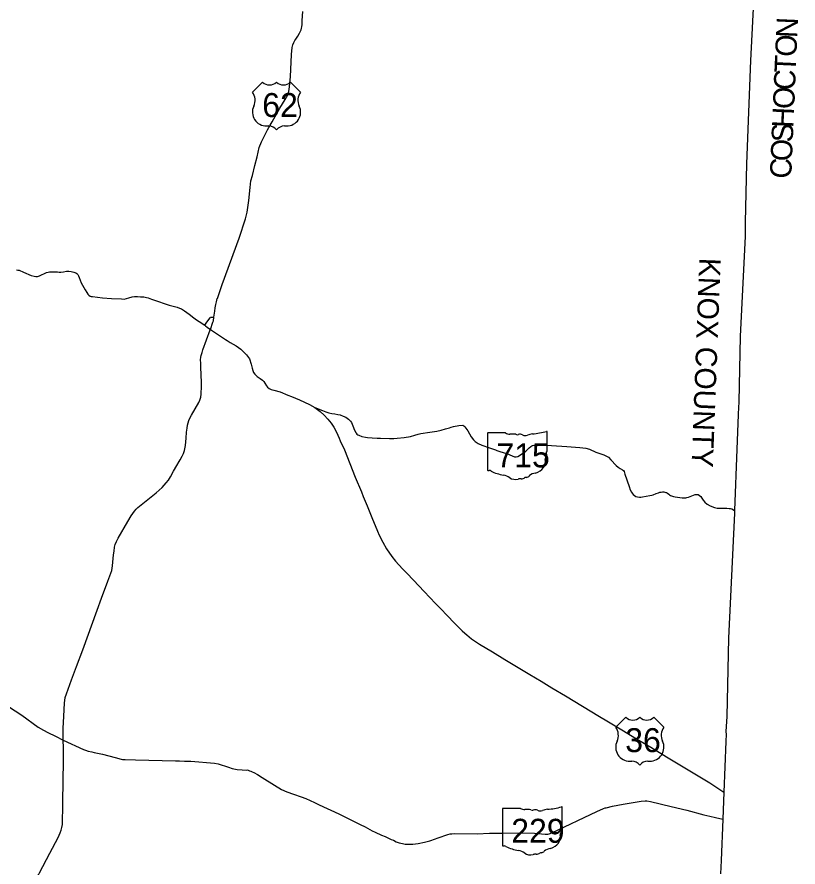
# Model space of a CAD drawing. Extents: x 1851937 to 2123937, y 789467 to 965467.
# Drawn here: x 2021685 to 2058232, y 848684 to 888471 of the extents above; entities that cross this region are included whole.
import ezdxf

# ---------------------------------------------------------------- set-up
doc = ezdxf.new("R2010")
doc.units = 0
for name, color, linetype in [('GM_X_County', 7, 'Continuous'), ('GM_X_County_Text', 7, 'Continuous'), ('GM_X_State_Location', 7, 'Continuous'), ('GM_X_State_Route', 7, 'Continuous'), ('GM_X_State_Shield', 7, 'Continuous'), ('GM_X_US_Location', 7, 'Continuous'), ('GM_X_US_Route', 7, 'Continuous'), ('GM_X_US_Shield', 7, 'Continuous')]:
    doc.layers.add(name, color=color, linetype=linetype)

msp = doc.modelspace()

# ---------------------------------------------------------------- linework, layer by layer
at = {"layer": 'GM_X_County'}
msp.add_lwpolyline([(2056177, 889807), (2056002, 886440), (2055829, 881600), (2055757, 878860), (2055763, 878218), (2055528, 873511), (2055458, 870451), (2055436, 869891), (2055434, 869842), (2055375, 868236), (2055262, 865369), (2055260, 865250), (2054985, 859397), (2054895, 855723), (2054855, 855032), (2054877, 854884), (2054856, 854579), (2054855, 854554), (2054764, 852183), (2054712, 850926), (2054638, 848994), (2054606, 848369)], dxfattribs=at)
at = {"layer": 'GM_X_State_Route'}
msp.add_line((2052003, 866233), (2052042, 866219), dxfattribs=at)
for points in [[(2035622, 870200), (2035980, 870055), (2036138, 869993), (2036279, 869945), (2036417, 869913), (2036558, 869892), (2036695, 869872), (2036812, 869847), (2036953, 869792), (2037068, 869733), (2037193, 869644), (2037289, 869554), (2037333, 869488), (2037394, 869337), (2037480, 869134), (2037541, 869022), (2037562, 868988), (2037591, 868947), (2037634, 868917), (2037676, 868894), (2037828, 868834), (2037993, 868797), (2038083, 868790), (2038305, 868768), (2038542, 868758), (2038695, 868755), (2039115, 868743), (2039321, 868736), (2039479, 868750), (2039806, 868794), (2040101, 868837), (2040308, 868894), (2040463, 868945), (2040583, 868978), (2040689, 868997), (2040897, 869025), (2041337, 869092), (2041531, 869128), (2041735, 869189), (2041920, 869248), (2042003, 869277), (2042114, 869305), (2042363, 869352), (2042545, 869368)], [(2042545, 869368), (2042594, 869335), (2042642, 869290), (2042692, 869229), (2042775, 869098), (2042941, 868820), (2043046, 868684), (2043125, 868603), (2043165, 868565), (2043271, 868507), (2043441, 868437), (2043799, 868311), (2044072, 868207), (2044145, 868174)], [(2044145, 868174), (2044228, 868146), (2044485, 868066), (2044650, 868020), (2044748, 867974), (2044966, 867882), (2045049, 867884), (2045115, 867905), (2045347, 868044), (2045496, 868148), (2045657, 868302), (2045738, 868374), (2045780, 868397), (2045815, 868412), (2045863, 868423), (2045947, 868426), (2046333, 868432), (2046443, 868437), (2046694, 868418), (2047415, 868366), (2048030, 868319), (2048311, 868286), (2048478, 868237), (2048778, 868099), (2048964, 868039), (2049141, 867976), (2049274, 867922), (2049359, 867871), (2049472, 867746), (2049726, 867482), (2049814, 867406), (2049915, 867340), (2050017, 867279), (2050061, 867246), (2050096, 867193), (2050135, 867079), (2050331, 866489), (2050383, 866338), (2050436, 866237), (2050475, 866182), (2050522, 866127), (2050584, 866072), (2050651, 866031), (2050728, 866006), (2050822, 865996), (2050879, 865998), (2050960, 866010), (2051306, 866077), (2051387, 866092), (2051453, 866112), (2051589, 866162), (2051710, 866205), (2051772, 866223), (2051831, 866236), (2051890, 866242), (2051958, 866240), (2052003, 866233)], [(2052042, 866219), (2052077, 866207), (2052132, 866177), (2052188, 866133), (2052226, 866106), (2052260, 866081), (2052309, 866057), (2052356, 866039), (2052403, 866025), (2052481, 866008), (2052812, 865968), (2052913, 865962), (2052979, 865966), (2053034, 865976), (2053116, 865997), (2053426, 866114), (2053479, 866122), (2053566, 866119), (2053626, 866069), (2053679, 866020), (2053734, 865955), (2053794, 865862), (2053875, 865765), (2053976, 865673), (2054118, 865595), (2054322, 865511), (2054443, 865484), (2054558, 865484), (2054697, 865479), (2054909, 865475), (2055012, 865470), (2055069, 865457), (2055134, 865442), (2055263, 865366)], [(2021285, 856194), (2021906, 855784), (2022683, 855235), (2022919, 855090), (2023123, 854987), (2023488, 854802), (2023844, 854619)], [(2023844, 854619), (2024790, 854189), (2024894, 854148), (2025009, 854111), (2025183, 854074), (2025303, 854043), (2025690, 853958), (2026273, 853807), (2026552, 853731), (2026625, 853722), (2026751, 853716), (2027226, 853703), (2029102, 853652), (2029292, 853649)], [(2029292, 853649), (2029522, 853642), (2029816, 853631), (2030924, 853540), (2031100, 853511), (2031577, 853355), (2031749, 853299), (2031907, 853260), (2031995, 853249), (2032223, 853231), (2032440, 853215), (2032465, 853231), (2032563, 853189), (2032633, 853168), (2032697, 853141), (2032773, 853106), (2032940, 853009), (2033160, 852878), (2033740, 852518), (2034066, 852310), (2034317, 852203), (2034631, 852090), (2034990, 851965), (2035205, 851885), (2035600, 851702), (2035822, 851600), (2036739, 851166), (2037747, 850679), (2037983, 850558), (2038310, 850375), (2038448, 850310), (2038748, 850177), (2038912, 850117), (2039196, 849977), (2039309, 849934), (2039428, 849865), (2039572, 849817), (2039718, 849779), (2039844, 849748), (2040005, 849748), (2040213, 849751), (2040464, 849784), (2040747, 849839), (2041001, 849914), (2041048, 849930), (2041401, 850045), (2041852, 850201), (2041963, 850234), (2042035, 850243), (2042166, 850249), (2043216, 850231), (2043791, 850266), (2043860, 850260), (2044148, 850272), (2044402, 850274), (2045208, 850282), (2045895, 850266), (2046400, 850216), (2046520, 850227), (2046586, 850240), (2046717, 850278), (2048813, 851279), (2049136, 851424), (2049202, 851449), (2049254, 851457), (2049547, 851531), (2050057, 851624), (2050901, 851771), (2051075, 851783), (2051166, 851780), (2051337, 851749), (2052303, 851516), (2053025, 851339), (2053826, 851132), (2054114, 851058), (2054374, 851004), (2054713, 850923)]]:
    msp.add_lwpolyline(points, dxfattribs=at)
at = {"layer": 'GM_X_State_Shield'}
for p, q in [((2043700, 868973), (2043700, 867272)), ((2044548, 869002), (2043727, 869002)), ((2046501, 868155), (2046501, 869045)), ((2046501, 868155), (2046501, 868155)), ((2047202, 850582), (2047202, 851472)), ((2044401, 851401), (2044401, 849699)), ((2045249, 851430), (2044428, 851430)), ((2047202, 850582), (2047202, 850582))]:
    msp.add_line(p, q, dxfattribs=at)
for centre, major_axis, start_param, end_param in [((2043732, 868977), (32.5, 0), 1.712693, 3.28349), ((2044743, 869200), (315, 0), 4.042523, 4.731795), ((2044848, 868047), (1130, 0), 1.404758, 1.657858), ((2045882, 868483), (598, 0), 1.699011, 2.107814), ((2045503, 871322), (2971, 0), 4.814394, 5.042369), ((2046470, 869048), (31.2, 0), 6.141152, 7.989035), ((2045104, 868986), (90.8, 0), 3.836095, 5.185415), ((2045237, 868789), (189, 0), 0.950623, 2.079405), ((2045481, 869059), (227, 0), 4.081561, 5.145723), ((2045670, 867669), (743, 0), 5.101752, 6.440018), ((2046613, 867782), (211, 0), 2.387724, 3.262537), ((2046494, 868089), (48.3, 0), 1.883978, 3.671073), ((2046187, 867977), (290, 0), 5.934695, 6.695948), ((2046468, 868151), (33.4, 0), 5.05454, 6.418171), ((2043732, 867268), (32.7, 0), 3.00124, 4.508301), ((2043737, 867442), (250, 0), 4.665946, 4.897461), ((2043788, 867174), (90.1, 0), 0.519207, 1.627899), ((2044926, 868702), (2146, 0), 4.195997, 4.488961), ((2044286, 866508), (671, 0), 0.823519, 1.323587), ((2045468, 867107), (240, 0), 4.937069, 5.64225), ((2045983, 866794), (407, 0), 1.647645, 2.488434), ((2045012, 867165), (426, 0), 4.026481, 4.996735), ((2045258, 866577), (350, 0), 1.495662, 1.94098), ((2045289, 867038), (227, 0), 4.691044, 5.507374), ((2045495, 866873), (63.9, 0), 1.147584, 2.315152), ((2046204, 853749), (2971, 0), 4.814394, 5.042369), ((2047171, 851476), (31.2, 0), 6.141152, 7.989035), ((2044433, 851404), (32.5, 0), 1.712693, 3.28349), ((2045444, 851627), (315, 0), 4.042523, 4.731795), ((2045548, 850475), (1130, 0), 1.404758, 1.657858), ((2045805, 851413), (90.8, 0), 3.836095, 5.185415), ((2045938, 851216), (189, 0), 0.950623, 2.079405), ((2046182, 851486), (227, 0), 4.081561, 5.145723), ((2046583, 850910), (598, 0), 1.699011, 2.107814), ((2047314, 850210), (211, 0), 2.387724, 3.262537), ((2047195, 850517), (48.3, 0), 1.883978, 3.671073), ((2046888, 850404), (290, 0), 5.934695, 6.695948), ((2047169, 850579), (33.4, 0), 5.05454, 6.418171), ((2046371, 850097), (743, 0), 5.101752, 6.440018), ((2044433, 849696), (32.7, 0), 3.00124, 4.508301), ((2044438, 849870), (250, 0), 4.665946, 4.897461), ((2044489, 849601), (90.1, 0), 0.519207, 1.627899), ((2045627, 851130), (2146, 0), 4.195997, 4.488961), ((2044987, 848935), (671, 0), 0.823519, 1.323587), ((2046684, 849222), (407, 0), 1.647645, 2.488434), ((2045713, 849593), (426, 0), 4.026481, 4.996735), ((2045959, 849005), (350, 0), 1.495662, 1.94098), ((2045990, 849465), (227, 0), 4.691044, 5.507374), ((2046196, 849301), (63.9, 0), 1.147584, 2.315152), ((2046168, 849535), (240, 0), 4.937069, 5.64225)]:
    msp.add_ellipse(centre, major_axis=major_axis, ratio=0.8, start_param=start_param, end_param=end_param, dxfattribs=at)
at = {"layer": 'GM_X_US_Route'}
msp.add_line((2041509, 860781), (2041833, 860433), dxfattribs=at)
for points in [[(2031059, 875297), (2031061, 875302), (2031284, 875944), (2032076, 878119), (2032379, 879016), (2032455, 879334), (2032530, 879874), (2032596, 880492), (2032632, 880804), (2032709, 881050), (2032822, 881524), (2032921, 881927), (2033019, 882363), (2033119, 882624), (2033197, 882778), (2033405, 883190), (2033534, 883406), (2033619, 883557), (2033985, 884196), (2034230, 884603), (2034355, 884826), (2034396, 884919), (2034428, 885076), (2034440, 885224), (2034480, 885675), (2034535, 886716), (2034563, 887049), (2034600, 887172), (2034645, 887282), (2034688, 887368), (2034728, 887432), (2034823, 887571), (2034910, 887716), (2034940, 887777), (2034978, 887866), (2035002, 887946), (2035011, 888009), (2035033, 888127), (2035035, 888308), (2035054, 888721)], [(2021662, 876636), (2021721, 876628), (2021785, 876616), (2021997, 876524), (2022342, 876374), (2022485, 876333), (2022568, 876323), (2022647, 876330), (2022740, 876355), (2023071, 876504), (2023145, 876534), (2023200, 876542), (2023265, 876546), (2023344, 876548), (2023575, 876535), (2023654, 876527), (2023729, 876530), (2023868, 876550), (2023997, 876569), (2024065, 876572), (2024110, 876569), (2024222, 876559), (2024344, 876530), (2024440, 876495), (2024492, 876457), (2024534, 876417), (2024567, 876361), (2024599, 876283), (2024688, 876026), (2024806, 875812), (2024875, 875703), (2024947, 875580), (2025001, 875498), (2025052, 875447), (2025109, 875410), (2025160, 875393), (2025213, 875383), (2025688, 875322), (2026107, 875292), (2026583, 875274), (2026695, 875271), (2026802, 875287), (2026918, 875325), (2027069, 875372), (2027179, 875385), (2027327, 875387), (2027461, 875375), (2027618, 875366), (2027738, 875345), (2027819, 875323), (2027983, 875262)], [(2027983, 875262), (2028077, 875227), (2028800, 874980), (2029174, 874884), (2029296, 874846), (2029385, 874810), (2029518, 874723), (2029736, 874558)], [(2030903, 874417), (2030946, 874697), (2030965, 874861), (2030988, 875011), (2031016, 875131), (2031059, 875297)], [(2029736, 874558), (2029954, 874397), (2030091, 874303), (2030205, 874224), (2030469, 874041), (2030511, 874010)], [(2030469, 874041), (2030576, 874186), (2030721, 874396), (2030738, 874413), (2030780, 874427), (2030835, 874424), (2030903, 874417)], [(2030726, 873828), (2030733, 873847), (2030857, 874188), (2030873, 874245), (2030903, 874417)], [(2030285, 872145), (2030281, 872272), (2030278, 872423), (2030290, 872543), (2030308, 872628), (2030344, 872768), (2030381, 872886), (2030726, 873828)], [(2030511, 874010), (2030583, 873957), (2030733, 873847), (2031436, 873383), (2031522, 873329)], [(2031522, 873329), (2031667, 873238), (2031938, 873080), (2032154, 872925), (2032420, 872665), (2032558, 872466), (2032646, 872214), (2032689, 872040), (2032724, 871927), (2032759, 871834), (2032808, 871752), (2032919, 871651), (2033061, 871552), (2033180, 871468), (2033238, 871407), (2033287, 871326), (2033354, 871209), (2033403, 871140), (2033489, 871080), (2033575, 871041), (2033705, 871009), (2033998, 870922), (2034361, 870777), (2034529, 870707), (2034905, 870545), (2035372, 870338), (2035622, 870200)], [(2029318, 867737), (2029412, 867909), (2029469, 868038), (2029519, 868179), (2029564, 868407), (2029597, 868756), (2029619, 869035), (2029645, 869225), (2029667, 869358), (2029692, 869467), (2029727, 869582), (2029770, 869691), (2029853, 869838), (2030187, 870433), (2030243, 870541), (2030289, 870681), (2030307, 870814), (2030324, 871192), (2030324, 871282), (2030318, 871362), (2030287, 872081), (2030285, 872145)], [(2035622, 870200), (2035872, 869998), (2036055, 869829), (2036235, 869640), (2036386, 869457), (2036506, 869278), (2036608, 869094), (2036699, 868905), (2036756, 868762), (2036812, 868628), (2037008, 868205), (2037510, 866924), (2037802, 866251), (2037890, 866034), (2038065, 865594), (2038290, 865049), (2038562, 864400), (2038640, 864213), (2038801, 863887), (2038983, 863580), (2039224, 863224), (2039403, 863002), (2039732, 862646), (2039927, 862440), (2040243, 862107), (2040744, 861581), (2041271, 861020), (2041509, 860781)], [(2023844, 854619), (2023850, 855183), (2023875, 855724), (2023908, 856371), (2023919, 856478), (2023943, 856611), (2023995, 856790), (2024231, 857449), (2024465, 858066), (2024765, 858844), (2025434, 860699), (2025634, 861264), (2025940, 862067), (2026120, 862561), (2026161, 862784), (2026204, 863295), (2026229, 863473), (2026255, 863652), (2026283, 863777), (2026340, 863918), (2026414, 864080), (2026869, 864851), (2027031, 865121), (2027099, 865229), (2027185, 865340), (2027265, 865427), (2027344, 865506), (2027736, 865824), (2028202, 866201), (2028471, 866451), (2028666, 866668), (2028769, 866797), (2028868, 866949), (2029014, 867216), (2029172, 867481)], [(2029172, 867481), (2029275, 867661), (2029318, 867737)], [(2041833, 860433), (2042141, 860112), (2042522, 859737), (2042643, 859627), (2042730, 859559), (2042956, 859370), (2043321, 859122), (2043935, 858748), (2044513, 858401), (2045688, 857689), (2046219, 857377), (2046718, 857073), (2047355, 856696), (2048936, 855736), (2049291, 855529), (2050061, 855062), (2050601, 854734), (2051347, 854288), (2052084, 853842), (2054110, 852617), (2054765, 852180)], [(2021421, 845836), (2022068, 847069), (2022278, 847551), (2022403, 847858), (2022439, 847929), (2022474, 847990), (2022532, 848078), (2022629, 848224), (2022689, 848316), (2022742, 848412), (2023222, 849335), (2023604, 850061), (2023662, 850170), (2023711, 850276), (2023758, 850401), (2023790, 850533), (2023809, 850673), (2023817, 850909), (2023831, 851404), (2023837, 851730), (2023865, 853646), (2023864, 853944), (2023857, 854259), (2023844, 854619)]]:
    msp.add_lwpolyline(points, dxfattribs=at)
at = {"layer": 'GM_X_US_Shield'}
for p, q in [((2033176, 885424), (2032709, 884957)), ((2034951, 884957), (2034484, 885424)), ((2033363, 883370), (2033456, 883370)), ((2034203, 883370), (2034297, 883370)), ((2050176, 855695), (2049709, 855228)), ((2051950, 855228), (2051483, 855695)), ((2050363, 853640), (2050456, 853640)), ((2051203, 853640), (2051296, 853640))]:
    msp.add_line(p, q, dxfattribs=at)
for centre, radius, start, end in [((2033503, 885758), 467, 225.573, 314.427), ((2034157, 885758), 467, 225.573, 314.427), ((2032174, 884582), 654, 334.5471, 35.0009), ((2035486, 884582), 654, 144.9991, 205.4529), ((2033356, 884023), 654, 154.8319, 270.6383), ((2034304, 884023), 654, 269.3617, 25.1681), ((2033456, 882903), 467, 36.8699, 90), ((2034203, 882903), 467, 90, 143.1301), ((2050503, 856029), 467, 225.573, 314.427), ((2051156, 856029), 467, 225.573, 314.427), ((2049173, 854853), 654, 334.5471, 35.0009), ((2052486, 854853), 654, 144.9991, 205.4529), ((2050355, 854294), 654, 154.8319, 270.6383), ((2051304, 854294), 654, 269.3617, 25.1681), ((2050456, 853173), 467, 36.8699, 90), ((2051203, 853173), 467, 90, 143.1301)]:
    msp.add_arc(centre, radius, start, end, dxfattribs=at)

# ---------------------------------------------------------------- texts
at = {"layer": 'GM_X_County_Text'}
for s, rotation, p in [('N', 87.5378, (2058195, 887476)), ('O', 87.5378, (2058157, 886593)), ('T', 87.5372, (2058125, 885845)), ('C', 87.5371, (2058090, 885032)), ('O', 87.5378, (2058052, 884148)), ('H', 87.5378, (2058014, 883265)), ('S', 87.5378, (2057985, 882588)), ('O', 87.5378, (2057947, 881704)), ('C', 87.5371, (2057912, 880891)), ('KNOX COUNTY', 267.8289, (2053620, 877211))]:
    msp.add_text(s, height=1000, rotation=rotation, dxfattribs=at).set_placement(p)
at = {"layer": 'GM_X_State_Location'}
for s in ['s', 'r']:
    msp.add_text(s, height=1, dxfattribs=at).set_placement((2045082, 867776))
msp.add_text('715', height=1, rotation=0, dxfattribs=at).set_placement((2044729, 867703))
at = {"layer": 'GM_X_State_Shield'}
for s, p in [('715', (2044117, 867392)), ('229', (2044813, 849819))]:
    msp.add_text(s, height=1120.7, dxfattribs=at).set_placement(p)
at = {"layer": 'GM_X_US_Location'}
for s, p in [('0', (2033830, 884133)), ('/', (2033830, 884133)), ('0', (2025457, 860769)), ('/', (2025457, 860769)), ('0', (2052072, 853856)), ('/', (2052072, 853856))]:
    msp.add_text(s, height=1, dxfattribs=at).set_placement(p)
for s, p in [('62', (2033623, 883926)), ('36', (2051866, 853649))]:
    msp.add_text(s, height=1, rotation=0, dxfattribs=at).set_placement(p)
at = {"layer": 'GM_X_US_Shield'}
for s, p in [('62', (2033160, 883790)), ('36', (2050146, 854061))]:
    msp.add_text(s, height=1120.7, dxfattribs=at).set_placement(p)

doc.saveas('drawing.dxf')
